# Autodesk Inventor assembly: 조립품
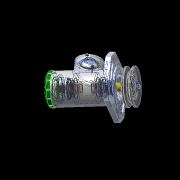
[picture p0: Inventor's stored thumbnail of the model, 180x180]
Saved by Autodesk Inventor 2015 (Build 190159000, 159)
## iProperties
Created: 2017-10
Part Number: 조립품
Document SubType Name: Assembly
Designer: Administrator
Author: Administrator
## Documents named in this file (20)
- C:\Users\Administrator\Desktop\471007V1038\조립품.iam
- C:\Users\Administrator\Desktop\471007V1038\본체.ipt
- C:\Users\Administrator\Desktop\471007V1038\축.ipt
- C:\Users\Administrator\Desktop\471007V1038\와셔 10x21.ipt
- C:\Users\Administrator\Desktop\471007V1038\너트 M10.ipt
- C:\Users\Administrator\Desktop\471007V1038\부시2.ipt
- C:\Users\Administrator\Desktop\471007V1038\부시1.ipt
- C:\Users\Administrator\Desktop\471007V1038\베어링 15 x 35 x 11.ipt
- C:\Users\Administrator\Desktop\471007V1038\멈춤링 35x1.6.ipt
- C:\Users\Administrator\Desktop\471007V1038\멈춤링 15 x 1.ipt
- C:\Users\Administrator\Desktop\471007V1038\V-벨트풀리.ipt
- C:\Users\Administrator\Desktop\471007V1038\와셔 4x16.ipt
- C:\Users\Administrator\Desktop\471007V1038\키 4 x 4 x 18.ipt
- C:\Users\Administrator\Desktop\471007V1038\볼트 M4 x 10.ipt
- C:\Users\Administrator\Desktop\471007V1038\오일 실 15 25 7.ipt
- C:\Users\Administrator\Desktop\471007V1038\사이드 커버.ipt
- 사이드 커버.ipt
- C:\Users\Administrator\Desktop\471007V1038\탑 커버.ipt
- C:\Users\Administrator\Desktop\471007V1038\와셔 3x6.ipt
- C:\Users\Administrator\Desktop\471007V1038\십자볼트 M3 x 10.ipt
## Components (2 placed, 2 different names)
1. V-벨트풀리:1 — 각도:1
2. ISO 4017 M4 x 10:1
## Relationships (1: Angle 1)
- 각도:1 [Angle]: V-벨트풀리:1
